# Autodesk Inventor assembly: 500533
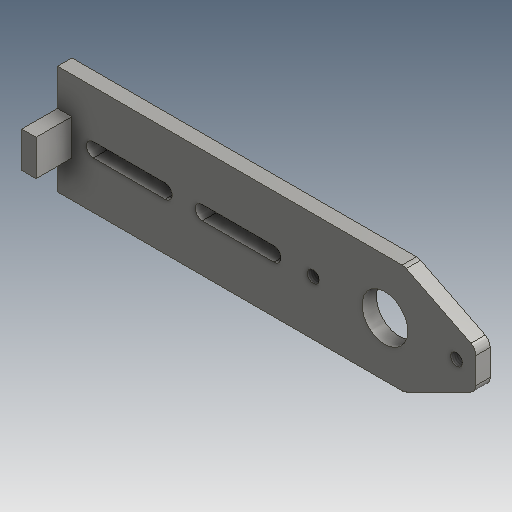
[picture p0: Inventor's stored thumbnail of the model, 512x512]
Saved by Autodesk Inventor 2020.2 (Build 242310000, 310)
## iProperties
Created: 1999-11
Part Number: 500533
Description: WMT--A,FH,CV,115,013,030,BELT_TENSIONER,BRNG_MNT
Document SubType Name: Assembly
Designer: mpflueger
Mass: 1526.06 g
Surface Area: 511.003 cm^2
Volume: 194.899 cm^3
Density: 7.83 g/cm^3
Control State: 0
Master: False
Checked Out: False
Shininess: 0.0
Length Units: 11272
Angle Units: 11279
Time Units: 11290
Mass Units: 11286
Length Display Precision: 3
Angle Display Precision: 2
Compacted: True
Dimensions: 3x1,4x11,5 in
Mass: 3,364 lb
Density: 0.0
Volumn: 0.0
Area: 0.0
PropertySet Name: Model Information
Author: mpflueger
Revision Number: -
Title: WMT--A,FH,CV,115,013,030,BELT_TENSIONER,BRNG_MNT
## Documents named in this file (3)
- D:\07 - DEMODATEN\OTX 2019 - Dataset - UPDATE - Dez2019\Designs\07-Packing machine\500533.iam
- D:\07 - DEMODATEN\OTX 2019 - Dataset - UPDATE - Dez2019\Designs\07-Packing machine\Parts\ADSK-011484.ipt
- D:\07 - DEMODATEN\OTX 2019 - Dataset - UPDATE - Dez2019\Designs\07-Packing machine\Parts\ADSK-011483.ipt
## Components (2 placed, 2 different names)
1. ADSK-011483:1 — Mate:1, Flush:1, Fluchtend:2
2. ADSK-011484:1 — Mate:1, Flush:1, Fluchtend:2
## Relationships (3: Flush 2, Mate 1)
- Mate:1: ADSK-011483:1 ↔ ADSK-011484:1
- Flush:1: ADSK-011483:1 ↔ ADSK-011484:1
- Fluchtend:2 [Flush]: ADSK-011483:1 ↔ ADSK-011484:1
